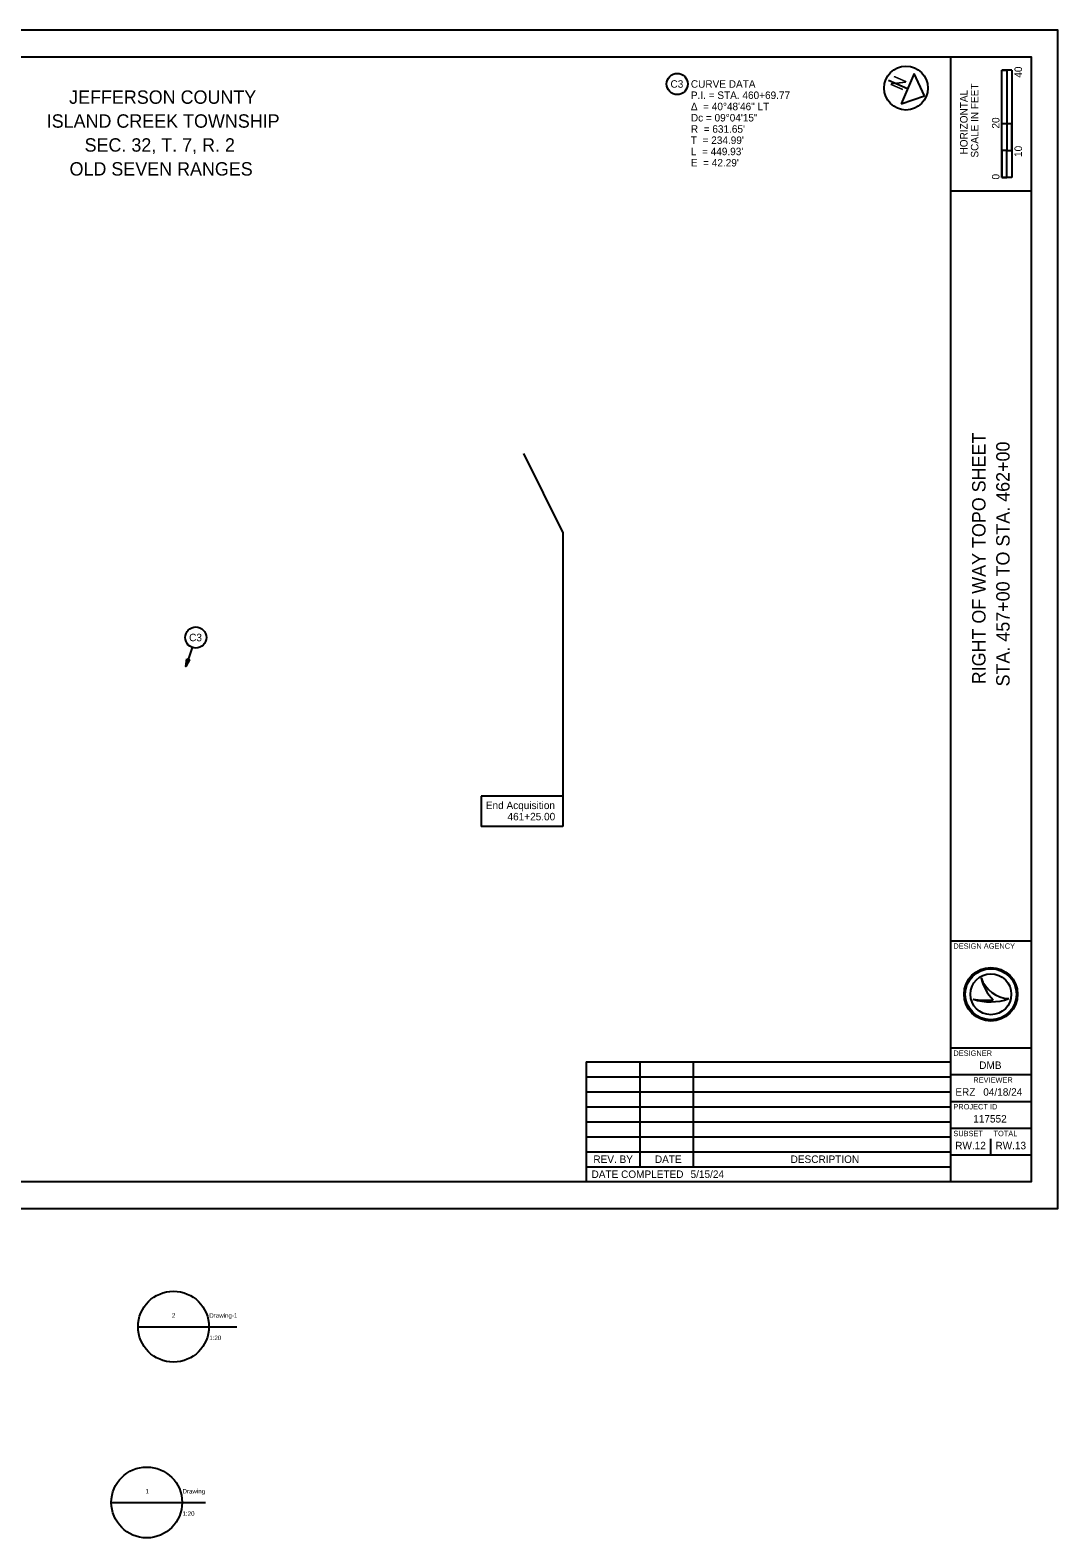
# Model space of a CAD drawing. Extents: x 0 to 680, y -123 to 440.
# Drawn here: x 296 to 680, y -123 to 440 of the extents above; entities that cross this region are included whole.
import ezdxf

# ---------------------------------------------------------------- set-up
doc = ezdxf.new("R2010")
doc.units = 0
for name, color, linetype in [('DV_X_Property_Line', 7, 'Continuous'), ('SH_Border', 7, 'Continuous'), ('SH_Cut_Line', 7, 'Continuous'), ('SH_Data', 7, 'Continuous'), ('SH_Text', 7, 'Continuous')]:
    doc.layers.add(name, color=color, linetype=linetype)

msp = doc.modelspace()

# ---------------------------------------------------------------- linework, layer by layer
at = {"layer": 'DV_X_Property_Line'}
msp.add_circle((623.31, 418.38), 8.2, dxfattribs=at)
at = {"layer": 'SH_Border'}
for p, q in [((640, 10), (640, 430)), ((640, 380), (670, 380)), ((640, 100), (670, 100)), ((640, 60), (670, 60)), ((640, 50), (670, 50)), ((640, 40), (670, 40)), ((640, 30), (670, 30)), ((640, 20), (670, 20))]:
    msp.add_line(p, q, dxfattribs=at)
msp.add_lwpolyline([(30, 430), (670, 430), (670, 10), (30, 10)], close=True, dxfattribs=at)
at = {"layer": 'SH_Cut_Line'}
msp.add_lwpolyline([(0, 0), (680, 0), (680, 440), (0, 440)], close=True, dxfattribs=at)
at = {"layer": 'SH_Data'}
for p, q in [((659.13, 385), (659.13, 425)), ((662.88, 425), (659.13, 425)), ((659.13, 405), (659.13, 425)), ((659.13, 425), (661, 425)), ((661, 425), (661.02, 425)), ((661.02, 425), (661.02, 405)), ((662.88, 425), (662.88, 385)), ((661.02, 405), (659.13, 405)), ((662.87, 405), (661, 405)), ((661, 405), (661, 395)), ((662.87, 395), (662.87, 405)), ((661, 395), (659.13, 395)), ((659.13, 395), (659.13, 385)), ((661, 385), (661, 395)), ((661, 395), (662.87, 395)), ((662.88, 385), (659.13, 385)), ((659.13, 385), (661, 385)), ((651.35, 86.19), (651.35, 86.19)), ((655, 80), (655, 80)), ((648.34, 78.19), (648.34, 78.19)), ((661.75, 78.37), (661.75, 78.37)), ((655, 20), (655, 26))]:
    msp.add_line(p, q, dxfattribs=at)
for radius in [10, 9.54, 9.54, 7.64]:
    msp.add_circle((655, 80), radius, dxfattribs=at)
for centre, radius, start, end in [((662.32, 89.95), 11.6, 198.9257, 198.9319), ((666.93, 89.4), 15.91, 191.6379, 191.6421), ((662.32, 89.95), 11.6, 198.9319, 267.1657), ((666.93, 89.4), 15.91, 191.6421, 226.0947), ((654.79, 97.4), 20.26, 251.4576, 290.0832), ((652.96, 103.09), 25.32, 259.4964, 259.4995), ((654.79, 97.4), 20.26, 251.4527, 251.4576), ((652.96, 103.09), 25.32, 259.4995, 276.6672)]:
    msp.add_arc(centre, radius, start, end, dxfattribs=at)
at = {"layer": 'SH_Text'}
for p, q in [((626.34, 423.78), (621.48, 412.48)), ((630.18, 415.43), (626.34, 423.78)), ((623.91, 418.13), (616.8, 421.19)), ((621.48, 412.48), (630.18, 415.43)), ((480.57, 281.91), (495.2, 252.33)), ((495.2, 252.33), (495.2, 142.69)), ((356.91, 209.46), (354.46, 202.39)), ((495.2, 153.94), (464.72, 153.94)), ((464.72, 153.94), (464.72, 142.69)), ((495.2, 142.69), (464.72, 142.69)), ((503.93, 54.8), (503.93, 10)), ((503.93, 54.8), (640, 54.8)), ((523.93, 54.8), (523.93, 15.6)), ((543.93, 54.8), (543.93, 15.6)), ((503.93, 49.2), (640, 49.2)), ((503.93, 43.6), (640, 43.6)), ((503.93, 38), (640, 38)), ((503.93, 32.4), (640, 32.4)), ((503.93, 26.8), (640, 26.8)), ((503.93, 21.2), (640, 21.2)), ((503.93, 15.6), (640, 15.6)), ((640, 10), (640, 10)), ((336.65, -44.13), (363.11, -44.13)), ((349.99, -44.13), (373.58, -44.13)), ((326.66, -109.76), (353.11, -109.76)), ((340, -109.76), (361.8, -109.76))]:
    msp.add_line(p, q, dxfattribs=at)
msp.add_lwpolyline([(354.85, 205.22), (355.9, 204.85), (354.46, 202.39)], close=True, dxfattribs=at)
for centre, radius in [((537.9, 419.9), 3.96), ((623.31, 418.38), 8.2), ((358.21, 213.21), 3.96), ((349.88, -44.13), 13.23), ((339.89, -109.76), 13.23)]:
    msp.add_circle(centre, radius, dxfattribs=at)

# ---------------------------------------------------------------- texts
at = {"layer": 'SH_Data'}
for s, height, p in [('40', 2.8, (666.61, 422.25)), ('HORIZONTAL', 2.8, (646.3, 393.58)), ('SCALE IN FEET', 2.8, (650.35, 392.41)), ('20', 2.8, (658.21, 403.25)), ('10', 2.8, (666.61, 392.65)), ('0', 2.8, (658.21, 384.23)), ('RIGHT OF WAY TOPO SHEET', 5, (653, 195.74)), ('STA. 457+00 TO STA. 462+00', 5, (662, 194.94))]:
    msp.add_text(s, height=height, rotation=90, dxfattribs=at).set_placement(p)
for s, height, p in [('             JEFFERSON COUNTY             ', 5, (286.77, 412.5)), ('           ISLAND CREEK TOWNSHIP          ', 5, (282.12, 403.57)), ('            SEC. 32, T. 7, R. 2           ', 5, (294.4, 394.63)), ('             OLD SEVEN RANGES             ', 5, (286.93, 385.7)), ('DESIGN AGENCY', 2, (641, 97)), ('DESIGNER', 2, (641, 57)), ('DMB', 2.8, (650.65, 52.1)), ('REVIEWER', 2, (648.44, 47)), ('04/18/24', 2.8, (652.16, 42.1)), ('ERZ', 2.8, (641.74, 42.1)), ('PROJECT ID', 2, (641, 37)), ('117552', 2.8, (648.42, 32.1)), ('SUBSET', 2, (641, 27)), ('TOTAL', 2, (656, 27)), ('RW.12', 2.8, (641.69, 22.1)), ('RW.13', 2.8, (656.7, 22.1))]:
    msp.add_text(s, height=height, dxfattribs=at).set_placement(p)
at = {"layer": 'SH_Text'}
msp.add_text('N', height=5, rotation=246.7033, dxfattribs=at).set_placement((619.16, 423.47))
for s, height, p in [('C3', 2.8, (535.4, 418.5)), ('CURVE DATA', 2.8, (543.01, 418.5)), ('P.I. = STA. 460+69.77', 2.8, (543.01, 414.3)), ('Δ  = 40°48\'46" LT', 2.8, (543.01, 410.1)), ('Dc = 09°04\'15"', 2.8, (543.01, 405.9)), ("T  = 234.99'", 2.8, (543.01, 397.5)), ("R  = 631.65'", 2.8, (543.01, 401.7)), ("L  = 449.93'", 2.8, (543.01, 393.3)), ("E  = 42.29'", 2.8, (543.01, 389.1)), ('C3', 2.8, (355.71, 211.81)), ('End Acquisition', 2.8, (466.48, 149.14)), ('461+25.00', 2.8, (474.57, 144.94)), ('REV. BY', 2.8, (506.61, 17)), ('DATE', 2.8, (529.59, 17)), ('DESCRIPTION', 2.8, (580.25, 17)), ('DATE COMPLETED', 2.8, (505.93, 11.4)), ('5/15/24                            ', 2.8, (542.89, 11.4)), ('2', 1.67, (349.29, -40.8)), ('Drawing-1', 1.667, (363.24, -40.8)), ('1:20', 1.667, (363.24, -49.13)), ('1', 1.67, (339.45, -106.42)), ('Drawing', 1.667, (353.24, -106.42)), ('1:20', 1.667, (353.24, -114.76))]:
    msp.add_text(s, height=height, dxfattribs=at).set_placement(p)

doc.saveas('drawing.dxf')
